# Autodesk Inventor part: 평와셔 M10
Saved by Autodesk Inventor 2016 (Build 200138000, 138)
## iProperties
Created: 2024-08
Part Number: 평와셔 M10
Material: 일반
Description: 평면 와셔
Document SubType Name: Modeling
Designer: pc-2
Density: 1 g/cm^3
Appearance: 기본값
Author: jhkim
Sending System: Autodesk Inventor 2025
Preprocessor: ST-DEVELOPER v20
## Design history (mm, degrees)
node "평와셔 M101"
node "솔리드1"
body "Solid1"
